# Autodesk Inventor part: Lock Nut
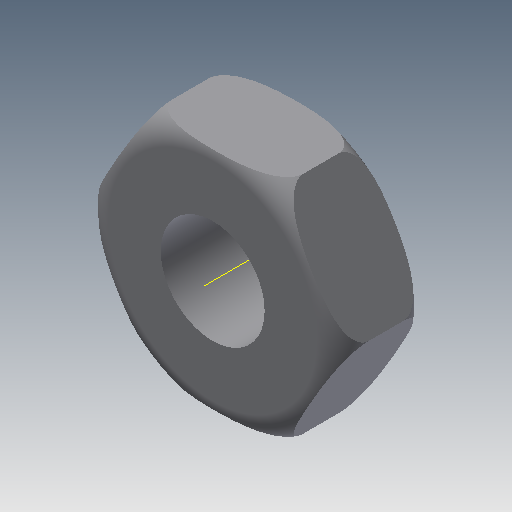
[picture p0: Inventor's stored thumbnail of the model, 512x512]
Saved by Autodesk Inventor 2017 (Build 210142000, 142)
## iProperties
Created: 2009-04
Part Number: Lock Nut
Document SubType Name: Modeling
Designer: Sham
Density: 1 g/cm^3
Material: Generic
Appearance: Default
Author: Sham
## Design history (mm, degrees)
sketch "Sketch1"
  geometry: L1 (7.5, 12.99)-(15, 0); L2 (15, 0)-(7.5, -12.99); L3 (7.5, -12.99)-(-7.5, -12.99); L4 (-7.5, -12.99)-(-15, 0); L5 (-15, 0)-(-7.5, 12.99); L6 (-7.5, 12.99)-(7.5, 12.99); C1 r 6 at (0, 0); 1 further point
  constraints: 12 end point, 1 centre point, 1 coincident, 13 other
  dimensions: "d0" = 30 distance of L1.end L4.end; "d1" = 12 diameter of C1
extrude "Extrusion1" new body sketch "Sketch1" distance "d2" = 10; taper "d3" = 0 deg
sketch "Sketch2"
  geometry: L1 (-12, 0)-(-12, -0.022); L2 (-15, 7)-(-15, 3); L3 (0, -2.87)-(0, 12.87) reference; A1 r 3 centre (-12, 7) between (-12, 10) and (-15, 7); A2 r 3 centre (-12, 3) between (-15, 3) and (-12, 0)
  constraints: 4 end point, 4 point on circle, 2 centre point, 1 tangent
revolve "Revolution1" sketch "Sketch2" stored, may be unused: angle "d7" = 90 deg
body "Solid1"
other parameters: "d6" = 90 deg
